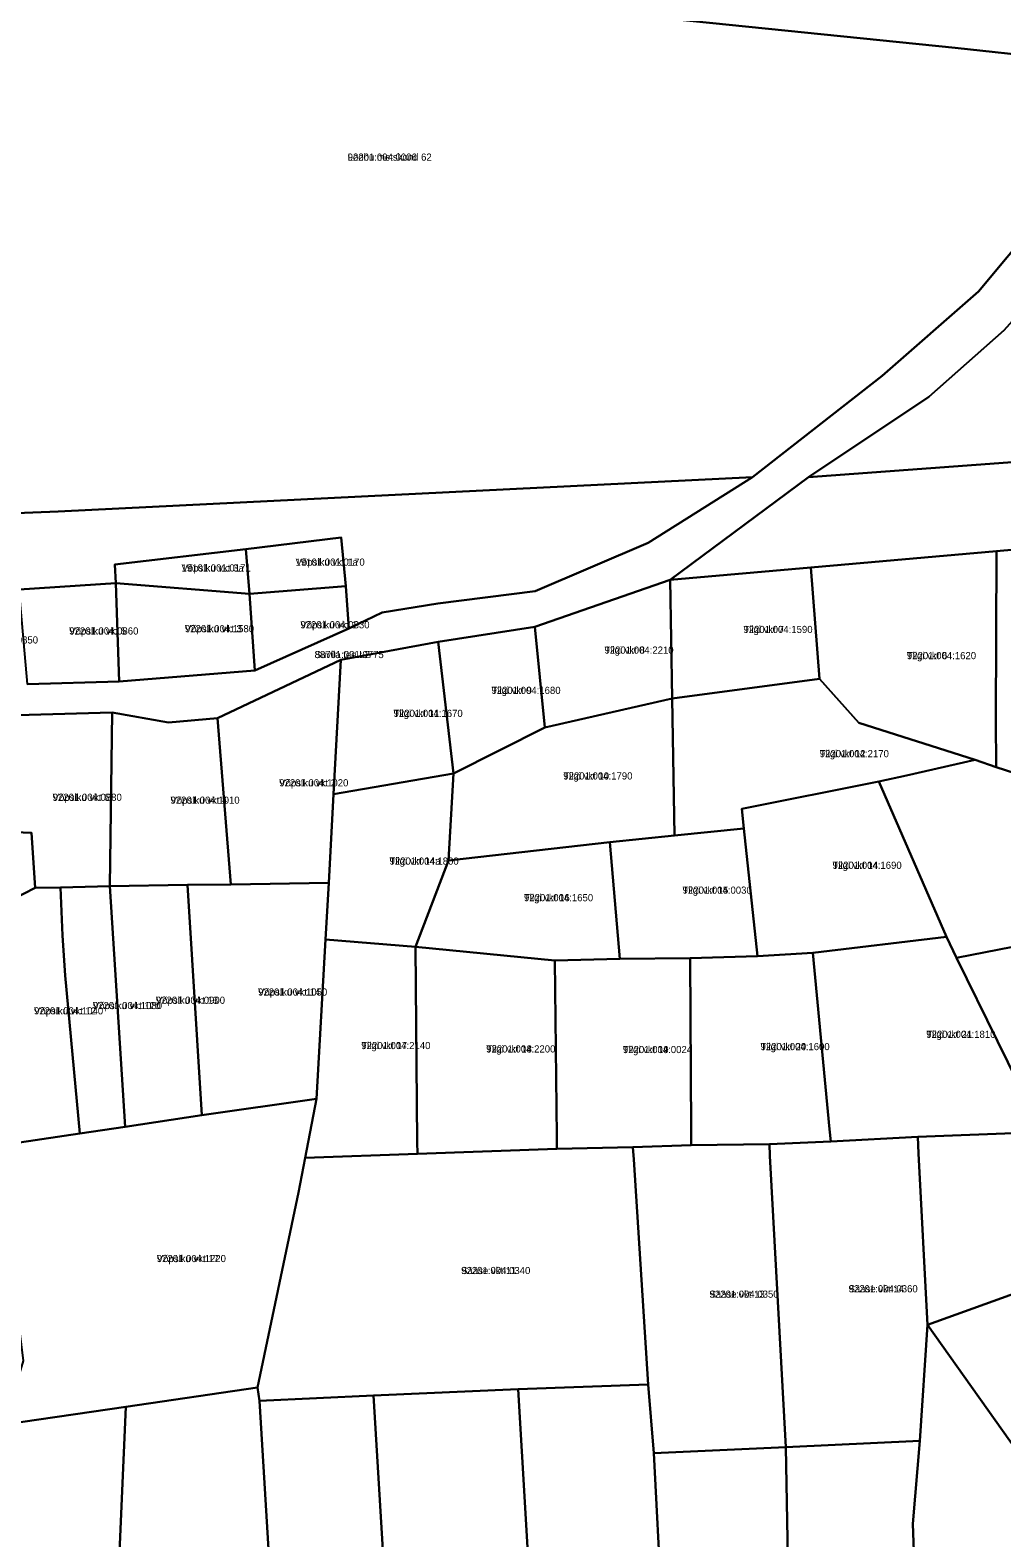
# Model space of a CAD drawing. Extents: x 601493 to 643081, y 6584980 to 6634019.
# Drawn here: x 610001.3 to 610205.1, y 6605427.7 to 6605743.8 of the extents above; entities that cross this region are included whole.
import ezdxf

# ---------------------------------------------------------------- set-up
doc = ezdxf.new("R2010")
doc.units = 0
for name, color, linetype in [('L_AADRESS', 7, 'Continuous'), ('PIIR', 7, 'Continuous'), ('TUNNUS', 7, 'Continuous')]:
    doc.layers.add(name, color=color, linetype=linetype)

msp = doc.modelspace()

# ---------------------------------------------------------------- linework, layer by layer
at = {"layer": 'PIIR'}
for points in [[(610234, 6605735.88), (610224.92, 6605718.63), (610200.13, 6605689.04), (610179.93, 6605671.33), (610152.8, 6605650.08), (610007.23, 6605642.89), (609916.86, 6605639.32), (609908.54, 6605793.58), (609940.79, 6605777.71), (609965.38, 6605768.93), (609991.64, 6605761.28), (610037.32, 6605756.23), (610195.26, 6605740.09)], [(610254.53, 6605734.73), (610266.17, 6605735.06), (610283.31, 6605696.84), (610287.89, 6605684.93), (610297.5, 6605659.86), (610164.51, 6605650.07), (610189.72, 6605666.95), (610205.55, 6605680.91), (610222.84, 6605700.29), (610234.19, 6605717.47), (610249.14, 6605734.93)], [(610164.51, 6605650.07), (610297.5, 6605659.86), (610303.57, 6605654.66), (610312.97, 6605657.53), (610318.71, 6605637.3), (610298.29, 6605641.47), (610272.21, 6605640.5), (610265.64, 6605639.99), (610233.6, 6605637.22), (610203.92, 6605634.6), (610164.97, 6605631.15), (610135.51, 6605628.57)], [(609916.86, 6605639.32), (610007.23, 6605642.89), (610152.8, 6605650.08), (610130.89, 6605636.35), (610107.22, 6605626.17), (610086.79, 6605623.63), (610075.1, 6605621.75), (610068.15, 6605618.37), (610067.52, 6605627.27), (610066.53, 6605637.45), (610046.56, 6605635), (610019.11, 6605631.81), (610019.32, 6605627.9), (609999.03, 6605626.57), (609980.21, 6605625.15), (609973.23, 6605603.88), (609966.33, 6605602.77), (609954.34, 6605603.92), (609943.14, 6605602.56), (609942.31, 6605615.03), (609918.27, 6605613.17), (609917.44, 6605628.88)], [(610047.34, 6605625.65), (610046.56, 6605635), (610066.53, 6605637.45), (610067.52, 6605627.27)], [(610203.77, 6605599.26), (610203.92, 6605634.6), (610233.6, 6605637.22), (610235.26, 6605590.9), (610235.6, 6605579.07), (610203.83, 6605589.28)], [(610019.32, 6605627.9), (610019.11, 6605631.81), (610046.56, 6605635), (610047.34, 6605625.65)], [(610166.8, 6605607.82), (610164.97, 6605631.15), (610203.92, 6605634.6), (610203.77, 6605599.26), (610203.83, 6605589.28), (610199.44, 6605590.81), (610175.09, 6605598.58)], [(610166.8, 6605607.82), (610135.92, 6605603.71), (610135.51, 6605628.57), (610164.97, 6605631.15)], [(610020.02, 6605607.29), (610000.76, 6605606.7), (609999.03, 6605626.57), (610019.32, 6605627.9)], [(610020.02, 6605607.29), (610019.32, 6605627.9), (610047.34, 6605625.65), (610048.45, 6605609.55)], [(610048.45, 6605609.55), (610047.34, 6605625.65), (610067.52, 6605627.27), (610068.15, 6605618.37)], [(610107.16, 6605618.73), (610135.51, 6605628.57), (610135.92, 6605603.71), (610109.22, 6605597.63)], [(610086.87, 6605615.59), (610107.16, 6605618.73), (610109.22, 6605597.63), (610090.1, 6605587.99)], [(610066.47, 6605611.8), (610086.87, 6605615.59), (610090.1, 6605587.99), (610064.93, 6605583.65)], [(610064.93, 6605583.65), (610063.92, 6605565.09), (610043.43, 6605564.69), (610040.63, 6605599.55), (610066.47, 6605611.8)], [(610150.99, 6605576.46), (610136.4, 6605574.96), (610135.92, 6605603.71), (610166.8, 6605607.82), (610175.09, 6605598.58), (610199.44, 6605590.81), (610185.05, 6605587.59), (610179.24, 6605586.31), (610150.57, 6605580.58)], [(610090.1, 6605587.99), (610109.22, 6605597.63), (610135.92, 6605603.71), (610136.4, 6605574.96), (610122.89, 6605573.59), (610089.04, 6605569.73)], [(610001.59, 6605575.53), (609994.53, 6605575.84), (609993.56, 6605600.07), (610018.55, 6605600.75), (610018.06, 6605564.34), (610007.71, 6605564.11), (610002.42, 6605564)], [(610018.55, 6605600.75), (610030.32, 6605598.7), (610040.63, 6605599.55), (610043.43, 6605564.69), (610034.33, 6605564.61), (610018.06, 6605564.34)], [(610193.42, 6605553.76), (610179.24, 6605586.31), (610185.05, 6605587.59), (610199.44, 6605590.81), (610203.83, 6605589.28), (610235.6, 6605579.07), (610255.11, 6605560.84), (610230.64, 6605556.2), (610195.54, 6605549.33)], [(610063.92, 6605565.09), (610064.93, 6605583.65), (610090.1, 6605587.99), (610089.04, 6605569.73), (610082.15, 6605551.62), (610063.25, 6605553.17)], [(610153.79, 6605549.68), (610150.99, 6605576.46), (610150.57, 6605580.58), (610179.24, 6605586.31), (610193.42, 6605553.76), (610165.39, 6605550.35)], [(609957.77, 6605556.1), (609965.47, 6605577.51), (609994.53, 6605575.84), (610001.59, 6605575.53), (610002.42, 6605564), (609992.54, 6605558.98), (609972.65, 6605557.24)], [(610153.79, 6605549.68), (610139.72, 6605549.29), (610124.99, 6605549.1), (610122.89, 6605573.59), (610136.4, 6605574.96), (610150.99, 6605576.46)], [(610089.04, 6605569.73), (610122.89, 6605573.59), (610124.99, 6605549.1), (610111.32, 6605548.81), (610082.15, 6605551.62)], [(609992.54, 6605558.98), (610002.42, 6605564), (610007.71, 6605564.11), (610008.11, 6605554.01), (610008.7, 6605545.64), (610011.74, 6605512.52), (609994.37, 6605509.95)], [(610008.7, 6605545.64), (610008.11, 6605554.01), (610007.71, 6605564.11), (610018.06, 6605564.34), (610021.25, 6605513.93), (610011.74, 6605512.52)], [(610034.33, 6605564.61), (610037.31, 6605516.37), (610021.25, 6605513.93), (610018.06, 6605564.34)], [(610034.33, 6605564.61), (610043.43, 6605564.69), (610063.92, 6605565.09), (610063.25, 6605553.17), (610061.39, 6605519.77), (610037.31, 6605516.37)], [(610212.7, 6605514.42), (610195.54, 6605549.33), (610230.64, 6605556.2), (610255.11, 6605560.84), (610257.1, 6605559.12), (610264.52, 6605552.15), (610252.24, 6605532.84), (610231.4, 6605517.17), (610213.02, 6605513.29)], [(610168.93, 6605513.42), (610165.39, 6605550.35), (610193.42, 6605553.76), (610195.54, 6605549.33), (610212.7, 6605514.42), (610213.02, 6605513.29), (610211.12, 6605512.73), (610187.45, 6605511.78), (610169.17, 6605510.83)], [(610061.39, 6605519.77), (610063.25, 6605553.17), (610082.15, 6605551.62), (610082.5, 6605510.75), (610082.53, 6605508.27), (610058.99, 6605507.43)], [(610082.5, 6605510.75), (610082.15, 6605551.62), (610111.32, 6605548.81), (610111.72, 6605511.86), (610111.75, 6605509.31), (610082.53, 6605508.27)], [(610111.32, 6605548.81), (610124.99, 6605549.1), (610139.72, 6605549.29), (610139.89, 6605513.16), (610139.9, 6605510.06), (610127.72, 6605509.65), (610111.75, 6605509.31), (610111.72, 6605511.86)], [(610139.89, 6605513.16), (610139.72, 6605549.29), (610153.79, 6605549.68), (610165.39, 6605550.35), (610168.93, 6605513.42), (610169.17, 6605510.83), (610156.32, 6605510.27), (610139.9, 6605510.06)], [(610058.99, 6605507.43), (610057.58, 6605500.17), (610049.03, 6605459.29), (610021.37, 6605455.21), (609995.96, 6605451.54), (609999.94, 6605464.84), (609994.37, 6605509.95), (610011.74, 6605512.52), (610021.25, 6605513.93), (610037.31, 6605516.37), (610061.39, 6605519.77)], [(610187.59, 6605508.29), (610187.45, 6605511.78), (610211.12, 6605512.73), (610213.02, 6605513.29), (610213.63, 6605512.35), (610224.73, 6605485.11), (610189.49, 6605472.42)], [(610049.39, 6605456.44), (610049.03, 6605459.29), (610057.58, 6605500.17), (610058.99, 6605507.43), (610082.53, 6605508.27), (610111.75, 6605509.31), (610127.72, 6605509.65), (610127.89, 6605507.07), (610130.87, 6605459.9), (610103.67, 6605458.92), (610073.32, 6605457.62)], [(610130.87, 6605459.9), (610127.89, 6605507.07), (610127.72, 6605509.65), (610139.9, 6605510.06), (610156.32, 6605510.27), (610156.4, 6605507.82), (610159.77, 6605446.78), (610132.1, 6605445.52)], [(610156.4, 6605507.82), (610156.32, 6605510.27), (610169.17, 6605510.83), (610187.45, 6605511.78), (610187.59, 6605508.29), (610189.49, 6605472.42), (610187.86, 6605448.11), (610159.77, 6605446.78)], [(610189.49, 6605472.42), (610224.73, 6605485.11), (610227.16, 6605479.27), (610236.17, 6605456.97), (610237.38, 6605453.78), (610211.34, 6605441.61)], [(610187.99, 6605386.66), (610186.4, 6605430.65), (610187.86, 6605448.11), (610189.49, 6605472.42), (610211.34, 6605441.61), (610212.45, 6605426.19), (610215.53, 6605388.7), (610215.74, 6605386.18), (610188.09, 6605384.17)], [(610018.01, 6605378.33), (610021.37, 6605455.21), (610049.03, 6605459.29), (610049.39, 6605456.44), (610054.12, 6605379.3), (610054.22, 6605377.94), (610017.87, 6605374.91)], [(610078.02, 6605380.19), (610073.32, 6605457.62), (610103.67, 6605458.92), (610108.22, 6605381.94), (610108.37, 6605379.94), (610078.09, 6605378.99)], [(610108.22, 6605381.94), (610103.67, 6605458.92), (610130.87, 6605459.9), (610132.1, 6605445.52), (610135.28, 6605383.48), (610135.4, 6605381.5), (610108.37, 6605379.94)], [(610049.39, 6605456.44), (610073.32, 6605457.62), (610078.02, 6605380.19), (610078.09, 6605378.99), (610054.22, 6605377.94), (610054.12, 6605379.3)], [(609991.91, 6605378.66), (609995.96, 6605451.54), (610021.37, 6605455.21), (610018.01, 6605378.33), (610017.87, 6605374.91), (609991.79, 6605375.64)], [(610135.28, 6605383.48), (610132.1, 6605445.52), (610159.77, 6605446.78), (610160.86, 6605385.02), (610160.92, 6605382.95), (610135.4, 6605381.5)], [(610160.86, 6605385.02), (610159.77, 6605446.78), (610187.86, 6605448.11), (610186.4, 6605430.65), (610187.99, 6605386.66), (610188.09, 6605384.17), (610160.92, 6605382.95)]]:
    msp.add_lwpolyline(points, close=True, dxfattribs=at)
for points in [[(609994.6, 6605776.04), (610064.24, 6605768.14), (610178.33, 6605756.82), (610206.94, 6605753.24), (610233.04, 6605752.07), (610254.91, 6605749.59), (610254.53, 6605734.73), (610249.14, 6605734.93), (610242.11, 6605735.12), (610234, 6605735.88), (610195.26, 6605740.09), (610037.32, 6605756.23), (609991.64, 6605761.28)], [(610000.76, 6605606.7), (610020.02, 6605607.29), (610048.45, 6605609.55), (610068.15, 6605618.37), (610075.1, 6605621.75), (610086.79, 6605623.63), (610107.22, 6605626.17), (610130.89, 6605636.35), (610152.8, 6605650.08), (610179.93, 6605671.33), (610200.13, 6605689.04), (610224.92, 6605718.63)], [(610205.55, 6605680.91), (610189.72, 6605666.95), (610164.51, 6605650.07), (610135.51, 6605628.57), (610107.16, 6605618.73), (610086.87, 6605615.59), (610066.47, 6605611.8), (610040.63, 6605599.55), (610030.32, 6605598.7), (610018.55, 6605600.75), (609993.56, 6605600.07)]]:
    msp.add_lwpolyline(points, dxfattribs=at)

# ---------------------------------------------------------------- texts
at = {"layer": 'L_AADRESS'}
for s, p in [('Loobu metskond 62', (610067.9, 6605716.45)), ('Võpsiku vkt 1a', (610056.98, 6605631.55)), ('Võpsiku vkt 3a', (610033.07, 6605630.32)), ('Võpsiku vkt 1', (610057.99, 6605618.41)), ('Võpsiku vkt 5', (610009.53, 6605617.11)), ('Võpsiku vkt 3', (610033.78, 6605617.59)), ('Tiigi vkt 7', (610150.87, 6605617.43)), ('Suvila tee L2', (610060.96, 6605612.17)), ('Tiigi vkt 8', (610121.74, 6605613.1)), ('Tiigi vkt 6', (610185.15, 6605611.94)), ('Tiigi vkt 9', (610098.04, 6605604.66)), ('Tiigi vkt 11', (610077.52, 6605599.84)), ('Tiigi vkt 12', (610166.87, 6605591.39)), ('Võpsiku vkt 2', (610053.55, 6605585.28)), ('Tiigi vkt 10', (610113.11, 6605586.72)), ('Võpsiku vkt 6', (610006.05, 6605582.24)), ('Võpsiku vkt 4', (610030.75, 6605581.64)), ('Tiigi vkt 14a', (610076.68, 6605568.87)), ('Tiigi vkt 14', (610169.55, 6605567.99)), ('Tiigi vkt 15', (610138.12, 6605562.78)), ('Tiigi vkt 16', (610104.87, 6605561.2)), ('Võpsiku vkt 13', (610027.69, 6605539.7)), ('Võpsiku vkt 14', (610049.12, 6605541.42)), ('Võpsiku vkt 12', (610002.14, 6605537.48)), ('Võpsiku vkt 12d', (610014.48, 6605538.59)), ('Tiigi vkt 17', (610070.76, 6605530.2)), ('Tiigi vkt 20', (610154.45, 6605529.98)), ('Tiigi vkt 21', (610189.21, 6605532.55)), ('Tiigi vkt 18', (610096.95, 6605529.49)), ('Tiigi vkt 19', (610125.61, 6605529.36)), ('Võpsiku vkt 17', (610027.88, 6605485.55)), ('Sääse vkt 11', (610091.7, 6605483.04)), ('Sääse vkt 13', (610143.75, 6605478.08)), ('Sääse vkt 14', (610172.91, 6605479.21))]:
    msp.add_text(s, height=1.5, dxfattribs=at).set_placement(p)
at = {"layer": 'TUNNUS'}
for s, p in [('92201:004:0006', (610067.9, 6605716.45)), ('19101:001:0170', (610056.98, 6605631.55)), ('19101:001:0171', (610033.07, 6605630.32)), ('92201:004:0860', (610009.53, 6605617.11)), ('92201:004:1580', (610033.78, 6605617.59)), ('92201:004:0330', (610057.99, 6605618.41)), ('92201:004:1590', (610150.87, 6605617.43)), ('92201:004:0850', (609988.49, 6605615.23)), ('88701:001:0775', (610060.96, 6605612.17)), ('92201:004:2210', (610121.74, 6605613.1)), ('92201:004:1620', (610185.15, 6605611.94)), ('92201:004:1680', (610098.04, 6605604.66)), ('92201:004:1670', (610077.52, 6605599.84)), ('92201:004:2170', (610166.87, 6605591.39)), ('92201:004:1020', (610053.55, 6605585.28)), ('92201:004:1790', (610113.11, 6605586.72)), ('92201:004:0880', (610006.05, 6605582.24)), ('92201:004:1010', (610030.75, 6605581.64)), ('92201:004:1800', (610076.68, 6605568.87)), ('92201:004:1690', (610169.55, 6605567.99)), ('92201:004:0030', (610138.12, 6605562.78)), ('92201:004:1650', (610104.87, 6605561.2)), ('92201:004:0900', (610027.69, 6605539.7)), ('92201:004:1050', (610049.12, 6605541.42)), ('92201:004:1040', (610002.14, 6605537.48)), ('92201:004:1080', (610014.48, 6605538.59)), ('92201:004:2140', (610070.76, 6605530.2)), ('92201:004:1600', (610154.45, 6605529.98)), ('92201:004:1810', (610189.21, 6605532.55)), ('92201:004:2200', (610096.95, 6605529.49)), ('92201:004:0024', (610125.61, 6605529.36)), ('92201:004:1220', (610027.88, 6605485.55)), ('92201:004:0340', (610091.7, 6605483.04)), ('92201:004:0350', (610143.75, 6605478.08)), ('92201:004:0360', (610172.91, 6605479.21))]:
    msp.add_text(s, height=1.5, dxfattribs=at).set_placement(p)

doc.saveas('drawing.dxf')
